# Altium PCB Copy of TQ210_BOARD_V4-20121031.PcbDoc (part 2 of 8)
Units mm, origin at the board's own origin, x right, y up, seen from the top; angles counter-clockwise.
Board outline 191.2 x 131.27 mm, 2 copper layers (TopLayer, BottomLayer); 362 components, 455 nets, 1594 pads, 630 vias.
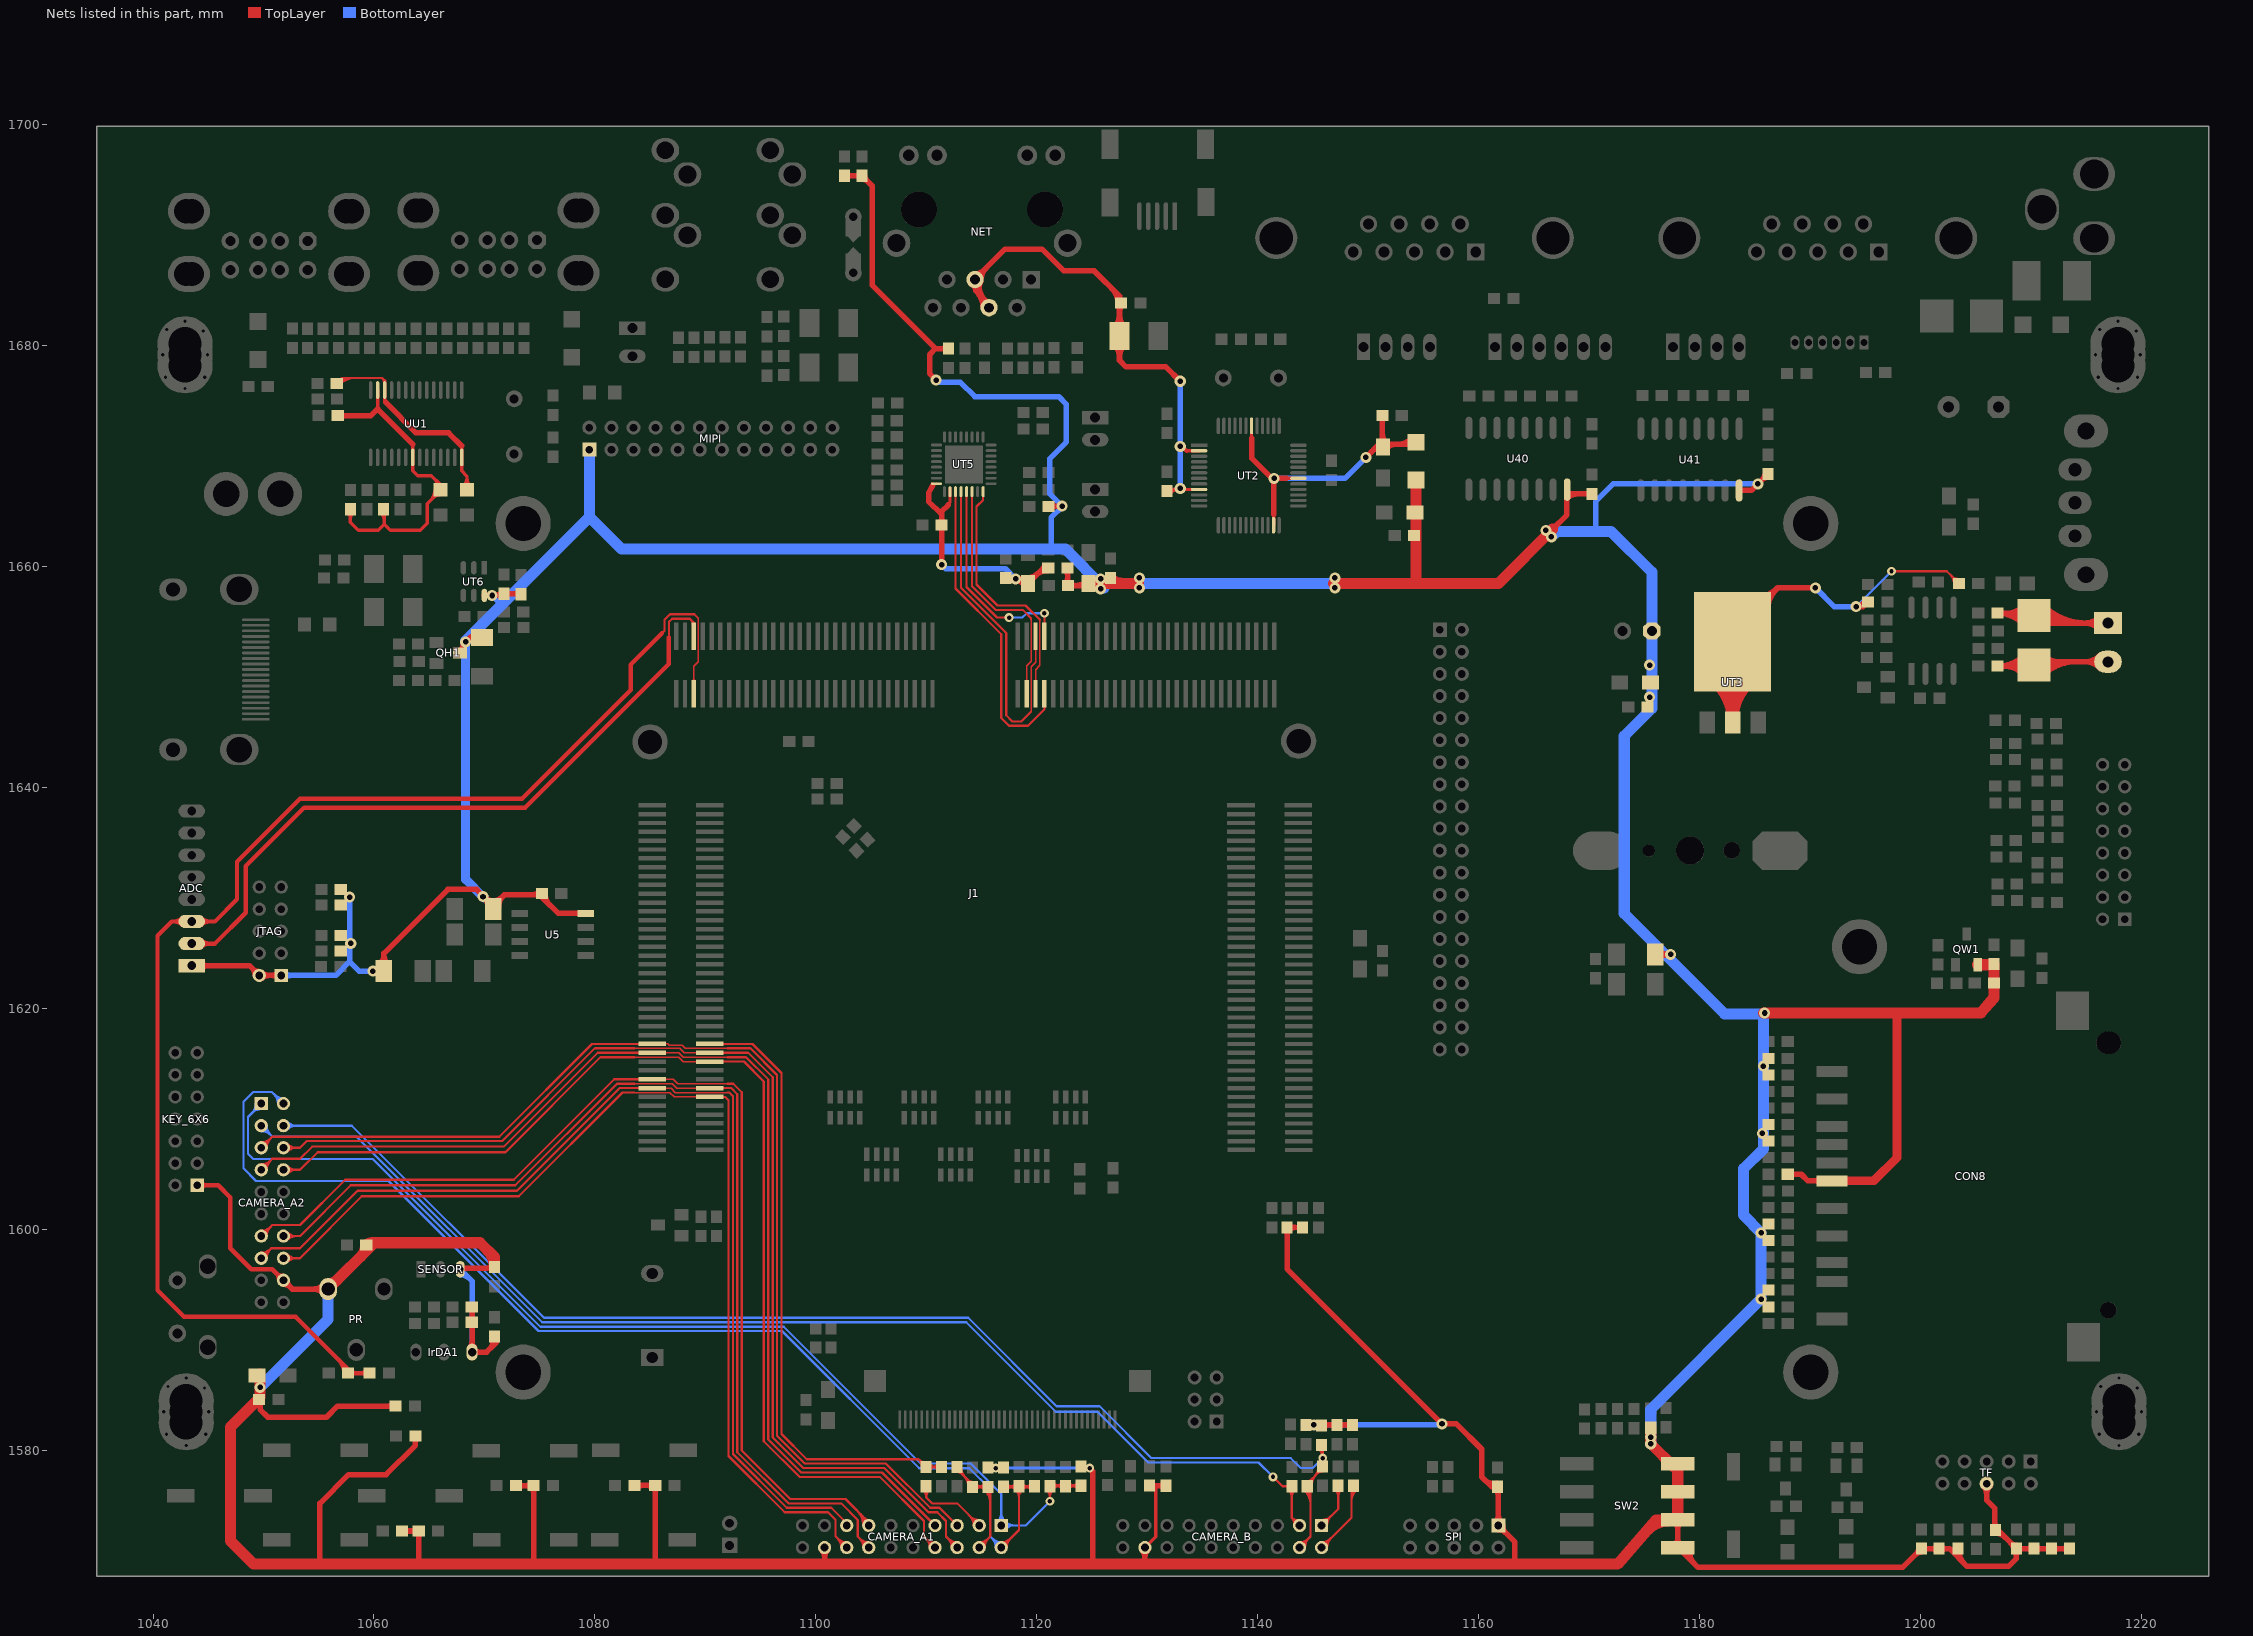
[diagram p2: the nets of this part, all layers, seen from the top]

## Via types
v1: diameter 1, hole 0.5, TopLayer to BottomLayer, 458 vias
v2: diameter 0.8, hole 0.4, TopLayer to BottomLayer, 172 vias

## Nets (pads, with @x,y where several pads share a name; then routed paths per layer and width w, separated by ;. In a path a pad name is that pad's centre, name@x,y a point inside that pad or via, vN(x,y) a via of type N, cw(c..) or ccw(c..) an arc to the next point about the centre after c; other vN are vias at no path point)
1V8_HUB: CU1.1 CU3.2 UU1.12 UU1.28 | length 25.5
  TopLayer w0.2: CU3.2@1056.54,1676.743 cw(c1057.406,1675.877) 1057.406,1677.102 ; CU3.2@1056.631,1676.602 1057.132,1677.102 1060.73,1677.102 1060.965,1676.867 ; CU3.2@1056.681,1676.602 cw(c1057.889,1675.395) 1057.889,1677.102 ; CU3.2@1056.823,1676.46 cw(c1058.372,1674.912) 1058.372,1677.102 ; 1060.726,1677.105 cw(c1060.271,1676.65) UU1.12@1060.915,1676.65 ; 1060.959,1674.943 1060.965,1674.949
  TopLayer w0.3: 1060.965,1674.949 UU1.12@1060.965,1676 1060.965,1676.867 ; 1067.95,1668.688 1068.419,1668.219 CU1.1@1068.419,1666.973 ; UU1.28@1067.95,1669.904 1067.95,1670.949 ; CU1.1@1068.1,1667.291 ccw(c1067.332,1668.059) 1068.419,1668.059 ccw(c1069.505,1668.059) CU1.1@1068.737,1667.291
  TopLayer w0.33: 1067.95,1668.688 UU1.28@1067.95,1669.904
  TopLayer w0.5: 1061.06,1674.917 1063.795,1672.131 1066.767,1672.131 1067.95,1670.949
3V3_HUB: CU2.1 CU5.1 RU18.2 RU19.2 UU1.13 UU1.21 | length 36.1
  TopLayer w0.3: RU18.2@1057.618,1664.911 cw(c1057.02,1664.313) 1057.865,1664.313 cw(c1058.71,1664.313) RU18.2@1058.112,1664.911 ; RU18.2@1057.865,1665.208 1057.865,1664.041 1058.596,1663.31 1060.374,1663.31 1060.933,1663.868 ; 1060.33,1674.289 UU1.13@1060.33,1676 ; RU19.2@1060.618,1664.911 cw(c1059.855,1664.148) 1060.933,1664.148 ; 1060.933,1664.478 cw(c1061.545,1664.478) RU19.2@1061.112,1664.911 ; RU19.2@1060.933,1665.316 1060.933,1663.868 ; 1063.505,1671.114 1063.505,1668.695 1063.95,1668.25 1065.2,1668.25 CU5.1@1065.95,1667.5 ; 1065.111,1665.996 ccw(c1064.13,1666.978) CU5.1@1065.518,1666.978 ; 1065.413,1666.298 cw(c1065.968,1665.743) CU5.1@1065.968,1666.528 ; 1065.421,1668.029 cw(c1064.457,1667.065) CU5.1@1065.818,1666.986 ; CU5.1@1066.056,1666.942 1064.828,1665.714 1064.828,1663.945 1064.193,1663.31 1061.492,1663.31 1060.933,1663.868
  TopLayer w0.5: CU2.1@1056.651,1673.657 1059.698,1673.657 1060.33,1674.289 1063.505,1671.114 ; CU2.1@1056.945,1673.521 cw(c1057.273,1673.194) 1057.273,1673.657 ; CU2.1@1056.945,1673.875 ccw(c1057.471,1674.401) 1057.471,1673.657
3V3_IO: ADC.1 C1.1 C3.1 C5.1 C6.1 C8.1 C9.1 C10.1 C11.1 C12.1 C15.1 C17.1 C111.1 C201.1 C202.1 C403.1 C413.1 C501.1 C517.1 C518.1 CAMERA_A1.18 CAMERA_A2.18 CAMERA_B.18 CM1.1 CM3.1 CMB1.1 CON8.4 D2.1 D3.1 D5.2 D7.2 IrDA1.3 JTAG.1 JTAG.2 KEY_6X6.1 L201.1 L421.1 L501.1 L503.2 L507.2 MIPI.1 PR.3 QH1.C QW1.2 R1.2 R2.2 R3.2 R4.2 R5.2 R6.2 R7.2 R8.2 R33.1 R61.1 R62.1 R63.1 R64.1 R210.1 R211.1 R331.1 RA3.2 RA5.2 RD1.1 RD2.1 RD3.1 RD4.1 RD5.1 RD6.1 RD7.1 RM19.1 RM20.1 RM23.1 RMB19.1 RMB20.1 RMB23.2 RO7.2 RO8.2 RS1.1 RS2.1 RS3.1 RS4.1 RS5.1 RS6.1 RS7.1 RS8.1 RT2.2 RT61.2 RW20.1 RW21.2 SENSOR.3 SPI.1 SW2.5 SW2.6 SW2.7 SW2.8 TF.6 U5.8 U40.16 U41.16 UT3.2 UT3.4 UT6.6 | length 1041.7
  TopLayer w0.2: v2(1197.4,1659.6) 1202.403,1659.6 R331.1@1203.498,1658.505 ; 1202.73,1659.274 cw(c1201.962,1658.505) R331.1@1203.048,1658.505 ; 1202.851,1659.153 ccw(c1203.448,1659.75) R331.1@1203.448,1658.905 ; R331.1@1203.071,1658.932 cw(c1202.645,1658.505) R331.1@1203.248,1658.505
  TopLayer w0.3: KEY_6X6.1@1044.318,1603.682 cw(c1045.086,1602.914) 1045.086,1604 cw(c1045.086,1605.086) KEY_6X6.1@1044.318,1604.318 ; CAMERA_A2.18@1051.35,1595.4 ccw(c1050.264,1595.4) 1051.032,1596.168 ccw(c1051.8,1596.936) CAMERA_A2.18@1051.8,1595.85 ; CAMERA_B.18@1129.8,1571.2 1130.783,1572.183 1130.783,1576.8
  TopLayer w0.4: KEY_6X6.1@1044,1604 1045.9,1604 1047,1602.9 1047,1598.3 1048.9,1596.4 1050.7,1596.4 ; 1050.8,1596.4 CAMERA_A2.18@1051.8,1595.4
  TopLayer w0.5: ADC.1@1043.502,1623.888 1048.728,1623.888 JTAG.2@1049.612,1623.004 ; ADC.1@1044.349,1623.64 cw(c1044.947,1623.043) 1044.947,1623.888 cw(c1044.947,1624.733) ADC.1@1044.349,1624.135 ; JTAG.2@1049.262,1623.004 ccw(c1048.417,1623.004) 1049.015,1623.601 ccw(c1049.612,1624.199) JTAG.2@1049.612,1623.354 ; C5.1@1049.473,1584.423 cw(c1048.926,1583.876) 1049.7,1583.876 ; JTAG.2@1049.612,1623 JTAG.1@1051.7,1623 ; C5.1@1049.7,1584.8 1049.7,1583.7 1050.4,1583 1055.7,1583 1056.711,1584.011 R3.2@1061.992,1584.011 ; JTAG.2@1049.859,1622.756 cw(c1050.448,1622.167) 1050.448,1623 ; JTAG.2@1049.859,1623.251 ccw(c1050.466,1623.857) 1050.466,1623 ; 1050.758,1623 ccw(c1050.758,1623.857) JTAG.1@1051.365,1623.251 ; 1050.776,1623 cw(c1050.776,1622.167) JTAG.1@1051.365,1622.756 ; CAMERA_A2.18@1051.8,1595.05 cw(c1051.8,1594.205) 1052.397,1594.803 cw(c1052.995,1595.4) CAMERA_A2.18@1052.15,1595.4 ; CAMERA_A2.18@1051.8,1595.4 1052.6,1594.6 PR.3@1055.852,1594.6 ; 1055.1,1569.7 1055.1,1575.2 1057.7,1577.8 1061.1,1577.8 1063.75,1580.45 R1.2@1063.75,1581.3 ; PR.3@1055.463,1594.211 ccw(c1054.524,1593.272) 1054.524,1594.6 ccw(c1054.524,1595.928) PR.3@1055.463,1594.989 ; D5.2@1060.546,1624.004 ccw(c1059.693,1624.857) 1060.9,1624.857 ccw(c1062.107,1624.857) D5.2@1061.254,1624.004 ; D5.2@1060.9,1623.4 1060.9,1625 1066.7,1630.8 1069.3,1630.8 1070.8,1629.3 1071.8,1630.3 1075,1630.3 1076.688,1628.612 U5.8@1079.194,1628.612 ; 1061.27,1584.011 cw(c1061.27,1583.37) R3.2@1061.723,1583.823 ; 1061.323,1584.011 ccw(c1061.323,1584.577) R3.2@1061.723,1584.177 ; R2.2@1062.55,1572.7 R4.2@1064.05,1572.7 1064.05,1569.7 ; R2.2@1062.777,1572.523 cw(c1063.204,1572.096) 1063.204,1572.7 cw(c1063.204,1573.304) R2.2@1062.777,1572.877 ; R1.2@1063.573,1581.123 cw(c1063.146,1580.696) 1063.75,1580.696 cw(c1064.354,1580.696) R1.2@1063.927,1581.123 ; R4.2@1063.823,1572.523 ccw(c1063.396,1572.096) 1063.396,1572.7 ccw(c1063.396,1573.304) R4.2@1063.823,1572.877 ; R4.2@1063.873,1572.523 cw(c1063.446,1572.096) 1064.05,1572.096 cw(c1064.654,1572.096) R4.2@1064.227,1572.523 ; QH1.C@1067.782,1652.401 ccw(c1067.376,1653) v1@1068.1,1653 ; SENSOR.3@1067.808,1596.4 1067.908,1596.5 1070.145,1596.5 ; SENSOR.3@1067.914,1596.294 cw(c1068.412,1595.796) 1068.412,1596.5 ; QH1.C@1068.1,1652.1 v1@1068.1,1653 ; v1@1068.275,1653.175 cw(c1068.775,1652.675) D2.1@1069.229,1653.217 ; v1@1068.334,1653.234 cw(c1069.283,1652.284) 1069.55,1653.6 ccw(c1069.127,1653.095) 1068.661,1653.561 ; IrDA1.3@1068.698,1589.336 ccw(c1068.257,1589.777) 1068.88,1589.777 ccw(c1069.503,1589.777) IrDA1.3@1069.062,1589.336 ; RA3.2@1068.723,1591.423 cw(c1068.345,1591.045) 1068.88,1591.045 ; RA3.2@1068.723,1591.777 ccw(c1068.345,1592.155) 1068.88,1592.155 ; RA5.2@1068.723,1592.823 cw(c1068.345,1592.445) 1068.88,1592.445 ; RA5.2@1068.85,1593 1068.88,1592.97 IrDA1.3@1068.88,1588.9 ; 1068.88,1590.948 cw(c1069.552,1590.948) RA3.2@1069.077,1591.423 ; 1068.88,1592.252 ccw(c1069.552,1592.252) RA3.2@1069.077,1591.777 ; 1068.88,1592.348 cw(c1069.552,1592.348) RA5.2@1069.077,1592.823 ; IrDA1.3@1069,1588.9 1070.2,1588.9 1070.9,1589.6 CM1.1@1070.9,1590.3 ; IrDA1.3@1069.062,1588.718 cw(c1069.503,1588.277) 1069.503,1588.9 cw(c1069.503,1589.523) IrDA1.3@1069.062,1589.082 ; D2.1@1069.113,1653.357 ccw(c1068.7,1653.128) 1068.7,1653.6 ; D2.1@1069.113,1653.843 cw(c1068.7,1654.072) 1068.7,1653.6 ; D2.1@1069.8,1653.6 1068.7,1653.6 ; v1@1069.911,1630.189 cw(c1068.972,1629.25) D7.2@1070.3,1629.25 ; UT6.6@1069.995,1657.412 RT61.2@1071.588,1657.412 ; v1@1070.032,1630.068 ccw(c1070.8,1630.836) 1070.8,1629.75 ccw(c1070.8,1630.836) 1071.568,1630.068 ; 1070.525,1589.225 ccw(c1069.963,1589.787) CM1.1@1070.676,1590.139 ; C501.1@1070.6,1596.4 C501.1@1070.7,1596.3 ; CM1.1@1070.723,1590.073 cw(c1070.296,1589.646) 1070.9,1589.646 cw(c1071.504,1589.646) CM1.1@1071.077,1590.073 ; v1@1070.948,1657.412 ccw(c1070.948,1658.35) RT61.2@1071.612,1657.687 ; 1071.018,1589.718 ccw(c1070.623,1590.113) CM1.1@1071.124,1590.361 ; D7.2@1071.3,1629.25 cw(c1072.628,1629.25) 1071.689,1630.189 ; RT61.2@1071.789,1657.56 CM3.1@1073.253,1657.56 ; RT61.2@1071.965,1657.383 cw(c1072.392,1656.956) 1072.392,1657.56 cw(c1072.392,1658.164) RT61.2@1071.965,1657.737 ; 1072.697,1657.56 ccw(c1072.697,1658.166) CM3.1@1073.125,1657.737 ; 1072.7,1657.56 cw(c1072.7,1656.959) CM3.1@1073.125,1657.384 ; R5.2@1072.85,1576.8 R6.2@1074.45,1576.8 1074.45,1569.7 ; R5.2@1073.077,1576.623 cw(c1073.504,1576.196) 1073.504,1576.8 cw(c1073.504,1577.404) R5.2@1073.077,1576.977 ; R6.2@1074.223,1576.623 ccw(c1073.796,1576.196) 1073.796,1576.8 ccw(c1073.796,1577.404) R6.2@1074.223,1576.977 ; R6.2@1074.273,1576.623 cw(c1073.846,1576.196) 1074.45,1576.196 cw(c1075.054,1576.196) R6.2@1074.627,1576.623 ; 1074.305,1630.3 ccw(c1074.305,1631.245) C9.1@1074.973,1630.577 ; C9.1@1075.5,1630.4 ccw(c1076.949,1630.4) 1075.924,1629.376 ; R7.2@1083.574,1576.824 R8.2@1085.474,1576.824 1085.474,1569.7 ; R7.2@1083.801,1576.647 cw(c1084.228,1576.22) 1084.228,1576.824 cw(c1084.228,1577.428) R7.2@1083.801,1577.001 ; R8.2@1085.247,1576.647 ccw(c1084.82,1576.22) 1084.82,1576.824 ccw(c1084.82,1577.428) R8.2@1085.247,1577.001 ; R8.2@1085.297,1576.647 cw(c1084.87,1576.22) 1085.474,1576.22 cw(c1086.078,1576.22) R8.2@1085.651,1576.647 ; CAMERA_A1.18@1100.553,1570.953 cw(c1099.955,1570.355) 1100.8,1570.355 cw(c1101.645,1570.355) CAMERA_A1.18@1101.047,1570.953 ; 1100.8,1569.9 CAMERA_A1.18@1100.8,1571.2 ; R210.1@1102.6,1695.4 R211.1@1103.9,1695.4 ; R210.1@1102.777,1695.223 cw(c1103.204,1694.796) 1103.204,1695.4 cw(c1103.204,1696.004) R210.1@1102.777,1695.577 ; R211.1@1104.023,1695.223 ccw(c1103.596,1694.796) 1103.596,1695.4 ccw(c1103.596,1696.004) R211.1@1104.023,1695.577 ; R211.1@1104.2,1695.1 cw(c1104.2,1694.376) 1104.712,1694.888 ; R211.1@1104.2,1695.4 1105.1,1694.5 1105.1,1685.5 1110.85,1679.75 ; R211.1@1104.45,1695.35 ccw(c1104.933,1695.35) R211.1@1104.591,1695.009 ; v1(1110.9,1676.9) 1110.3,1677.5 1110.3,1679.2 1110.85,1679.75 ; L503.2@1111.823,1679.573 ccw(c1111.396,1679.146) 1111.396,1679.75 ccw(c1111.396,1680.354) L503.2@1111.823,1679.927 ; L503.2@1112,1679.75 1110.85,1679.75 ; L507.2@1121.078,1665.476 v1@1122.324,1665.476 ; L507.2@1121.305,1665.299 cw(c1121.731,1664.872) 1121.731,1665.476 cw(c1121.731,1666.08) L507.2@1121.305,1665.653 ; RT2.2@1122.623,1658.477 ccw(c1122.196,1658.904) 1122.8,1658.904 ccw(c1123.404,1658.904) RT2.2@1122.977,1658.477 ; L501.1@1122.623,1659.723 cw(c1122.196,1659.296) 1122.8,1659.296 cw(c1123.404,1659.296) L501.1@1122.977,1659.723 ; RT2.2@1122.8,1658.35 L501.1@1122.8,1659.9 ; RT2.2@1122.85,1658.3 C517.1@1124.7,1658.3 ; RT2.2@1123.077,1658.123 cw(c1123.504,1657.696) 1123.504,1658.3 cw(c1123.504,1658.904) RT2.2@1123.077,1658.477 ; 1123.594,1658.3 ccw(c1123.594,1659.479) C517.1@1124.428,1658.645 ; 1123.947,1658.3 cw(c1123.947,1657.62) C517.1@1124.428,1658.101 ; RM20.1@1124,1578.4 v2(1124.8,1578.4) 1125.1,1578.1 1125.1,1569.7 ; CAMERA_B.18@1129.553,1570.953 cw(c1128.955,1570.355) 1129.8,1570.355 cw(c1130.645,1570.355) CAMERA_B.18@1130.047,1570.953 ; 1129.7,1569.9 1129.8,1570 CAMERA_B.18@1129.8,1571.2 ; C11.1@1130.22,1576.8 R33.1@1131.7,1576.8 ; R33.1@1131.523,1576.623 ccw(c1131.096,1576.196) 1131.096,1576.8 ccw(c1131.096,1577.404) R33.1@1131.523,1576.977 ; RO8.2@1142.501,1599.945 cw(c1142.075,1599.518) 1142.678,1599.518 cw(c1143.282,1599.518) RO8.2@1142.855,1599.945 ; RO8.2@1142.678,1600.172 1142.678,1596.422 v1(1156.7,1582.4) ; RO8.2@1142.7,1600.2 RO7.2@1143.778,1600.172 ; RO8.2@1142.85,1599.991 cw(c1143.333,1599.482) 1143.351,1600.183 ; RO8.2@1142.86,1600.344 ccw(c1143.226,1600.693) 1143.213,1600.187 ; C8.1@1144.395,1582.311 1145.795,1582.311 1145.805,1582.3 RMB19.1@1148.8,1582.3 ; C8.1@1144.571,1582.134 cw(c1144.998,1581.707) 1144.998,1582.311 cw(c1144.998,1582.914) C8.1@1144.571,1582.487 ; v1@1145.171,1582.311 cw(c1145.171,1581.671) RMB23.2@1145.623,1582.123 ; v1@1145.222,1582.311 ccw(c1145.222,1582.878) RMB23.2@1145.623,1582.477 ; RMB23.2@1145.977,1582.123 cw(c1146.404,1581.696) 1146.404,1582.3 cw(c1146.404,1582.904) RMB23.2@1145.977,1582.477 ; RMB20.1@1147.023,1582.123 ccw(c1146.596,1581.696) 1146.596,1582.3 ccw(c1146.596,1582.904) RMB20.1@1147.023,1582.477 ; RMB20.1@1147.377,1582.123 cw(c1147.804,1581.696) 1147.804,1582.3 cw(c1147.804,1582.904) RMB20.1@1147.377,1582.477 ; RMB19.1@1148.423,1582.123 ccw(c1147.996,1581.696) 1147.996,1582.3 ccw(c1147.996,1582.904) RMB19.1@1148.423,1582.477 ; L201.1@1153.992,1667.486 cw(c1153.118,1666.612) 1154.354,1666.612 cw(c1155.59,1666.612) L201.1@1154.716,1667.486 ; C202.1@1154.039,1662.647 cw(c1153.277,1661.885) 1154.354,1661.885 ; C202.1@1154.039,1663 ccw(c1153.277,1663.762) 1154.354,1663.762 ; C201.1@1154.12,1664.651 cw(c1153.556,1664.087) 1154.354,1664.087 ; C201.1@1154.12,1665.196 ccw(c1153.556,1665.76) 1154.354,1665.76 ; 1154.354,1658.546 1154.4,1658.5 ; 1154.354,1663.901 cw(c1155.415,1663.901) C201.1@1154.665,1664.651 ; 1154.354,1665.946 ccw(c1155.415,1665.946) C201.1@1154.665,1665.196 ; v1@1156.7,1582.3 v1(1156.7,1582.4) ; 1160.585,1577.315 ccw(c1161.403,1578.132) C12.1@1161.655,1577.004 ; C12.1@1161.515,1576.554 ccw(c1161.19,1576.294) 1161.19,1576.71 ; C12.1@1161.515,1576.866 cw(c1161.19,1577.126) 1161.19,1576.71 ; SPI.1@1161.527,1573.471 ccw(c1160.844,1574.151) 1161.807,1574.154 ; C12.1@1161.534,1576.483 cw(c1160.891,1575.836) 1161.803,1575.839 ; C12.1@1161.71,1576.71 1161.19,1576.71 ; SPI.1@1161.8,1572.815 cw(c1161.8,1571.886) 1162.457,1572.543 cw(c1163.114,1573.2) SPI.1@1162.185,1573.2 ; C12.1@1161.8,1576.8 1161.81,1573.19 1163.3,1571.7 1163.3,1569.8 ; 1161.807,1574.105 ccw(c1162.703,1574.108) SPI.1@1162.071,1573.473 ; 1166.7,1663.4 1168,1664.7 U40.16@1168,1666.9 ; U40.16@1168.067,1666.239 cw(c1168.938,1665.369) 1168.938,1666.6 ; U40.16@1168.1,1666.6 C403.1@1170.3,1666.6 ; C403.1@1170.123,1666.423 ccw(c1169.696,1665.996) 1169.696,1666.6 ccw(c1169.696,1667.204) C403.1@1170.123,1666.777 ; D3.1@1176,1624.9 v1(1177.4,1624.9) ; D3.1@1176.354,1624.546 cw(c1177.207,1623.693) 1177.207,1624.9 cw(c1177.207,1626.107) D3.1@1176.354,1625.254 ; SW2.8@1177.722,1578.478 1178.044,1578.156 ; SW2.5@1177.797,1571.427 ccw(c1177.199,1572.025) 1178.044,1572.025 ccw(c1178.889,1572.025) SW2.5@1178.291,1571.427 ; SW2.6@1177.797,1573.473 cw(c1177.199,1572.875) 1178.044,1572.875 cw(c1178.889,1572.875) SW2.6@1178.291,1573.473 ; SW2.5@1177.9,1571.662 ccw(c1178.163,1571.541) SW2.5@1177.958,1571.336 ; SW2.5@1178.044,1571.18 SW2.6@1178.044,1573.7 ; SW2.5@1178.044,1571.25 1179.894,1569.4 1198.4,1569.4 RD1.1@1200.1,1571.1 1202.65,1571.1 1204.25,1569.5 1208,1569.5 1208.7,1570.2 RD4.1@1208.7,1571.1 ; SW2.5@1178.354,1571.452 ccw(c1178.856,1571.22) SW2.5@1178.465,1570.829 ; SW2.5@1178.808,1571.243 ccw(c1179.55,1570.9) 1178.972,1570.322 ; SW2.5@1179.262,1571.033 ccw(c1180.244,1570.58) 1179.479,1569.815 ; U41.16@1183.6,1666.912 1184.712,1666.912 C413.1@1186.2,1668.4 ; UT3.4@1183.654,1656.353 ccw(c1184.314,1658.527) UT3.4@1185.92,1656.92 ; UT3.4@1183.799,1656.831 ccw(c1184.589,1659.432) 1186.51,1657.51 ; UT3.4@1183.944,1657.31 ccw(c1184.863,1660.336) 1187.1,1658.1 ccw(c1189.54,1655.66) UT3.4@1186.172,1654.908 ; UT3.4@1185.684,1654.799 cw(c1188.488,1655.425) UT3.4@1186.456,1657.456 ; 1185.688,1667.888 cw(c1186.2,1667.376) C413.1@1186.2,1668.1 ; C413.1@1185.809,1668.009 ccw(c1185.467,1668.35) C413.1@1185.95,1668.35 ; UT3.4@1186,1657 1187.1,1658.1 v1(1190.5,1658.1) ; C3.1@1188,1605 1189.229,1605 1189.824,1604.405 CON8.4@1191.995,1604.405 ; C3.1@1188.227,1604.823 cw(c1188.654,1604.396) 1188.654,1605 cw(c1188.654,1605.604) C3.1@1188.227,1605.177 ; CON8.4@1190.918,1604.228 ccw(c1190.491,1603.801) 1190.491,1604.405 ccw(c1190.491,1605.009) CON8.4@1190.918,1604.582 ; L421.1@1195.005,1656.906 cw(c1194.2,1657.293) v1(1194.2,1656.4) 1194.8,1656.4 L421.1@1195.2,1656.8 ; 1199.588,1570.588 cw(c1200.1,1570.076) RD1.1@1200.1,1570.8 ; RD1.1@1199.709,1570.709 ccw(c1199.367,1571.05) RD1.1@1199.85,1571.05 ; RD1.1@1200.277,1570.923 cw(c1200.704,1570.496) 1200.704,1571.1 cw(c1200.704,1571.704) RD1.1@1200.277,1571.277 ; RD2.1@1201.523,1570.923 ccw(c1201.096,1570.496) 1201.096,1571.1 ccw(c1201.096,1571.704) RD2.1@1201.523,1571.277 ; RD2.1@1201.877,1570.923 cw(c1202.304,1570.496) 1202.304,1571.1 cw(c1202.304,1571.704) RD2.1@1201.877,1571.277 ; RD3.1@1203.163,1571.13 ccw(c1203.818,1570.909) 1203.33,1570.42 ; RD3.1@1203.637,1570.97 ccw(c1204.672,1570.622) 1203.9,1569.85 ; TF.6@1205.739,1576.717 cw(c1205.082,1576.059) 1206.011,1576.059 cw(c1206.94,1576.059) TF.6@1206.283,1576.717 ; TF.6@1206.011,1576.989 1206.011,1575.489 1206.75,1574.75 1206.75,1573 1206.8,1573 RD4.1@1208.7,1571.1 ; 1206.072,1623.97 ccw(c1206.072,1624.602) RW21.2@1206.518,1624.155 ; 1206.111,1623.97 cw(c1206.111,1623.395) 1206.518,1623.802 cw(c1206.131,1623.415) 1206.679,1623.415 ; RW20.1@1206.502,1622.482 ccw(c1206.075,1622.909) 1206.679,1622.909 ccw(c1207.282,1622.909) RW20.1@1206.855,1622.482 ; RW21.2@1206.637,1623.97 RW21.2@1206.679,1623.929 ; 1206.679,1623.335 cw(c1207.338,1623.335) RW21.2@1206.872,1623.802 ; RW21.2@1206.679,1624.012 RW21.2@1206.695,1624.029 ; 1206.75,1573.574 ccw(c1207.524,1573.574) C6.1@1206.977,1573.027 ; C6.1@1206.8,1572.5 cw(c1206.8,1571.293) 1207.654,1572.146 ; 1208.188,1571.612 ccw(c1208.7,1572.124) RD4.1@1208.7,1571.4 ; RD4.1@1208.309,1571.491 cw(c1207.967,1571.15) RD4.1@1208.45,1571.15 ; RD4.1@1208.523,1570.873 cw(c1208.096,1570.446) 1208.7,1570.446 cw(c1209.304,1570.446) RD4.1@1208.877,1570.873 ; RD4.1@1208.877,1570.923 cw(c1209.304,1570.496) 1209.304,1571.1 cw(c1209.304,1571.704) RD4.1@1208.877,1571.277 ; RD5.1@1210.123,1570.923 ccw(c1209.696,1570.496) 1209.696,1571.1 ccw(c1209.696,1571.704) RD5.1@1210.123,1571.277 ; RD5.1@1210.477,1570.923 cw(c1210.904,1570.496) 1210.904,1571.1 cw(c1210.904,1571.704) RD5.1@1210.477,1571.277 ; RD6.1@1211.723,1570.923 ccw(c1211.296,1570.496) 1211.296,1571.1 ccw(c1211.296,1571.704) RD6.1@1211.723,1571.277 ; RD6.1@1212.077,1570.923 cw(c1212.504,1570.496) 1212.504,1571.1 cw(c1212.504,1571.704) RD6.1@1212.077,1571.277 ; RD7.1@1213.323,1570.923 ccw(c1212.896,1570.496) 1212.896,1571.1 ccw(c1212.896,1571.704) RD7.1@1213.323,1571.277 ; RD7.1@1213.5,1571.1 RD4.1@1208.7,1571.1 ; v1@1068.1,1653 1068.7,1653.6 ; 1070.145,1596.5 ccw(c1070.145,1597.31) 1070.718,1596.737 cw(c1070.145,1597.31) 1070.145,1596.5 ; v1(1156.7,1582.4) 1158,1582.4 1160.3,1580.1 1160.3,1577.6 1161.19,1576.71
  TopLayer w0.8: CON8.4@1191.9,1604.405 1195.805,1604.405 1197.9,1606.5 1197.9,1619.6
  TopLayer w1: 1047,1571.8 1049.1,1569.7 1172.6,1569.7 1176.1,1573.7 SW2.6@1178,1573.7 ; 1047,1571.9 1047,1582.1 1049.7,1584.8 C15.1@1049.7,1586.9 ; C15.1@1049.443,1586.69 cw(c1048.823,1586.07) v1@1049.7,1586.07 ; PR.3@1055.852,1594.6 1060.052,1598.8 ; PR.3@1055.852,1595.1 ccw(c1055.852,1596.307) 1056.706,1595.454 ; 1058.824,1597.572 ccw(c1057.797,1598.6) CMB1.1@1059.25,1598.6 ; 1070.297,1598.103 cw(c1068.855,1596.661) C501.1@1070.895,1596.661 ; C501.1@1070.895,1596.611 1070.895,1597.505 1069.6,1598.8 1060.052,1598.8 ; C517.1@1124.7,1658.5 v1@1129.2,1658.5 ; v1@1125.614,1658.5 ccw(c1125.614,1660.036) 1126.7,1658.95 ccw(c1127.786,1660.036) 1127.786,1658.5 ; v1@1146.9,1658.5 1161.8,1658.5 1166.7,1663.4 ; 1154.354,1658.546 L201.1@1154.354,1667.848 ; 1175.176,1572.643 cw(c1177.342,1570.748) SW2.6@1177.151,1573.62 ; 1175.519,1573.036 cw(c1176.856,1571.866) SW2.6@1177.129,1573.621 ; C1.1@1175.6,1582.05 v1(1175.6,1580.6) SW2.8@1177.722,1578.478 ; 1176.792,1579.408 cw(c1176.185,1578.8) SW2.8@1177.044,1578.8 ; SW2.6@1178.044,1573.72 1178.044,1578.156 ; UT3.4@1181.116,1649.865 cw(c1177.916,1645.9) UT3.2@1183.011,1645.9 cw(c1188.145,1645.9) UT3.4@1184.898,1649.876 ; UT3.4@1181.744,1650.644 cw(c1179.605,1647.992) 1183.011,1647.992 ; UT3.4@1183,1649.8 1183.011,1649.789 UT3.2@1183.011,1645.9 ; 1183.011,1648.008 cw(c1186.424,1648.008) UT3.4@1184.265,1650.651 ; v1@1185.8,1619.6 1205.5,1619.6 1206.679,1620.979 RW20.1@1206.679,1622.305 RW21.2@1206.679,1624.012 ; QW1.2@1205.206,1623.97 RW21.2@1206.637,1623.97 ; CMB1.1@1059.35,1598.6 cw(c1059.833,1598.117) 1059.833,1598.8 ccw(c1059.833,1598.117) CMB1.1@1059.35,1598.6 ; CMB1.1@1059.35,1598.6 ccw(c1059.521,1599.331) 1060.052,1598.8
  BottomLayer w0.2: v1(1194.2,1656.4) v2(1197.4,1659.6) v2@1197.6,1659.6
  BottomLayer w0.3: v2(1116.3,1578.4) v2(1124.8,1578.4)
  BottomLayer w0.5: JTAG.1@1051.612,1623.004 1056.544,1623.004 1057.8,1624.259 ; JTAG.1@1051.86,1622.756 cw(c1052.457,1622.159) 1052.457,1623.004 cw(c1052.457,1623.849) JTAG.1@1051.86,1623.251 ; v1(1057.8,1630.1) 1057.8,1624.259 ; v1(1059.9,1623.4) 1058.659,1623.4 1057.8,1624.259 ; SENSOR.3@1067.808,1595.9 cw(c1067.808,1594.693) 1068.662,1595.546 ; SENSOR.3@1067.808,1596.4 1068.88,1595.328 IrDA1.3@1068.88,1588.9 ; IrDA1.3@1068.698,1589.336 ccw(c1068.257,1589.777) 1068.88,1589.777 ccw(c1069.503,1589.777) IrDA1.3@1069.062,1589.336 ; v1(1070.7,1657.4) 1071.55,1656.55 ; v1@1111.2,1676.7 1113.1,1676.7 1114.4,1675.4 1122,1675.4 1122.7,1674.7 1122.7,1671.3 1121.2,1669.8 1121.2,1666.6 v1(1122.3,1665.5) ; 1121.3,1661.6 1121.3,1664.452 v1@1122.324,1665.476 ; v1(1145.1,1582.311) v1@1156.689,1582.311 ; v1@1166.4,1663.2 v1@1166.5,1663.2 ; 1170.6,1663.3 1170.6,1665.9 1172.2,1667.5 v1(1185.3,1667.5) ; v1(1190.5,1658.1) 1192.2,1656.4 v1(1194.2,1656.4)
  BottomLayer w0.8: v1(1068.3,1653.2) 1068.3,1631.7 v1@1070,1630
  BottomLayer w1: v1(1049.7,1585.7) 1055.852,1591.852 PR.3@1055.852,1594.6 ; v1@1068.3,1653.3 1079.5,1664.5 ; MIPI.1@1079.5,1670.6 1079.5,1664.5 ; v1@1126.1,1658.1 1122.6,1661.6 1082.4,1661.6 1079.5,1664.5 ; v1@1129.3,1658.5 1147.3,1658.5 ; v1@1166.5,1663.2 1172,1663.2 1175.694,1659.506 1175.694,1647.194 1173.2,1644.7 1173.2,1628.6 1182.3,1619.5 1185.8,1619.5 1185.8,1607.3 1184,1605.5 1184,1601.3 v1(1185.6,1599.7) v1@1185.6,1593.8 ; v1@1166.54,1663.34 1166.59,1663.29 1166.68,1663.2 v1@1166.89,1662.99 ; v1(1175.6,1580.6) 1175.6,1583.7 v1(1185.6,1593.7)
  other v1: 1175.6,1581.2 1185.7,1608.7 1185.8,1614.8 1185.9,1619.6 1057.9,1625.9 1069.871,1630.129 1175.5,1648.2 1175.5,1651.1 1125.8,1658 1129.3,1658.1 1147,1658.1 1125.8,1658.9 1129.3,1659 1147,1659 1166.6,1662.7 1166.1,1663.3
33V_AC97: C519.1 C520.1 C521.1 L501.2 UT5.8 UT5.10 | length 29.8
  TopLayer w0.2: 1110.598,1667.394 UT5.8@1110.928,1667.524
  TopLayer w0.3: 1112,1665.6 1112.153,1665.853 UT5.10@1112.153,1666.799 ; UT5.10@1112.148,1667.115 1112.149,1666.799 1112.153,1666.053
  TopLayer w0.5: 1110.598,1667.394 1110.228,1666.717 1110.228,1665.872 1111.4,1664.8 ; C520.1@1111.223,1663.623 cw(c1110.796,1663.196) 1111.4,1663.196 cw(c1112.004,1663.196) C520.1@1111.577,1663.623 ; C520.1@1111.223,1663.977 ccw(c1110.796,1664.404) 1111.4,1664.404 ccw(c1112.004,1664.404) C520.1@1111.577,1663.977 ; v1(1111.4,1660.2) 1111.4,1665 1112,1665.6 ; C521.1@1117.1,1658.9 1119.6,1658.9 1120.6,1659.9 L501.2@1121.05,1659.9 ; C521.1@1117.377,1659.127 ccw(c1117.924,1659.674) v1@1117.924,1658.9 ; C521.1@1117.611,1658.9 cw(c1117.611,1657.038) C519.1@1118.928,1658.355 ; C519.1@1119.2,1659.012 ccw(c1119.2,1660.248) 1120.074,1659.374 ; C519.1@1119.585,1658.627 cw(c1120.208,1658.627) C519.1@1119.767,1659.067 ; 1119.89,1659.19 cw(c1121,1658.081) L501.2@1121,1659.65
  BottomLayer w0.5: v1(1111.4,1660.2) 1111.78,1659.82 1117.18,1659.82 v1(1118.1,1658.9)
A1: 485.1 D421.2 R429.1 | length 30.9
  TopLayer w0.5: R429.1@1207.227,1655.623 cw(c1207.654,1655.196) 1207.654,1655.8 cw(c1207.654,1656.404) R429.1@1207.227,1655.977 ; 1207.765,1655.8 ccw(c1207.765,1658.135) D421.2@1209.416,1656.484 ; 1208.138,1655.8 cw(c1208.138,1653.615) D421.2@1209.748,1655.093 ; D421.2@1209.379,1654.755 ccw(c1207,1652.57) R429.1@1207,1655.8 1210.1,1655.8 1211,1654.9 485.1@1217,1654.9 ; D421.2@1210.477,1655.777 ccw(c1212.593,1657.893) 1212.593,1654.9 ; D421.2@1210.83,1656.13 ccw(c1213.801,1659.101) 1213.801,1654.9 ; D421.2@1211.184,1654.716 cw(c1211.628,1654.272) D421.2@1211.628,1654.9 ; D421.2@1211.184,1656.484 ccw(c1215.008,1660.308) 1215.008,1654.9 ; 485.1@1216.22,1654.37 ccw(c1214.939,1653.089) 1214.939,1654.9 ccw(c1214.939,1656.711) 485.1@1216.22,1655.43
AC97_BITCLK: J1.145 UT5.12 | length 31.8
  TopLayer w0.135: 1119.497,1646.903 1119.497,1650.942 1119.896,1651.34 J1.145@1119.896,1653.706
  TopLayer w0.2: UT5.12@1113.153,1666.799 1113.153,1658.097 1117.25,1654 1117.25,1646.55 1117.8,1646 1118.6,1646 1119.5,1646.9
AC97_RESETN: J1.148 UT5.11 | length 28.8
  TopLayer w0.2: UT5.11@1112.653,1666.799 1112.653,1658.032 1116.8,1653.884 1116.8,1646.3 1117.5,1645.6 1119.213,1645.6 1120.706,1647.093 J1.148@1120.706,1648.495 ; J1.148@1120.625,1647.385 cw(c1120.429,1647.189) 1120.706,1647.189 ; 1120.706,1647.239 cw(c1120.912,1647.239) J1.148@1120.766,1647.385
AC97_SDI: J1.146 UT5.16 | length 22.6
  TopLayer w0.135: J1.146@1119.896,1648.506 1119.896,1650.678 1120.295,1651.078 1120.295,1655.2
  TopLayer w0.2: UT5.16@1115.153,1666.799 1115.153,1666.053 1114.553,1665.453 1114.553,1658.394 1116.447,1656.5 1118.995,1656.5 1120.295,1655.2
AC97_SDO: J1.144 UT5.14 | length 22.2
  TopLayer w0.135: J1.144@1119.096,1648.506 1119.096,1651.042 1119.497,1651.444 1119.497,1655.335
  TopLayer w0.2: UT5.14@1114.153,1666.799 1114.153,1658.229 1116.281,1656.1 1118.732,1656.1 1119.497,1655.335 ; 1119.497,1655.256 1119.497,1655.303
AC97_SYNC: J1.147 UT5.13 | length 19.4
  TopLayer w0.2: UT5.13@1113.653,1666.799 1113.653,1658.163 1116.416,1655.4 v2(1117.5,1655.4) ; v2(1120.7,1655.8) J1.147@1120.706,1653.695
  BottomLayer w0.2: v2(1117.5,1655.4) 1118.7,1655.4 1119.1,1655.8 v2(1120.7,1655.8) v2@1120.5,1655.6
ADCIN0: ADC.2 J1.85 | length 65.8
  TopLayer w0.2: 1086.7,1653.6 1086.7,1655 1087,1655.3 1088.6,1655.3 1088.975,1654.925 J1.85@1088.975,1653.687 ; 1088.661,1655.239 cw(c1088.168,1654.747) J1.85@1088.865,1654.747
  TopLayer w0.4: ADC.2@1043.502,1625.888 1045.6,1625.888 1048.4,1628.688 1048.4,1632.9 1053.7,1638.2 1073.7,1638.2 1086.7,1651.2 1086.7,1653.6 ; ADC.2@1044.385,1625.605 cw(c1045.067,1624.922) 1045.067,1625.888 cw(c1045.067,1626.853) ADC.2@1044.385,1626.171
ADCIN1: ADC.3 CT6.2 J1.86 RA1.1 | length 134.2
  TopLayer w0.135: J1.86@1088.871,1649.641 ccw(c1088.645,1649.867) 1088.965,1649.867 ccw(c1089.284,1649.867) J1.86@1089.058,1649.641 ; J1.86@1088.965,1648.497 1088.965,1651.013 1089.366,1651.414 1089.366,1655.329 1088.995,1655.7
  TopLayer w0.2: 1086.078,1653.978 1086.3,1654.2 1086.3,1655.2 1086.8,1655.7 1088.995,1655.7
  TopLayer w0.4: ADC.3@1042.619,1627.605 ccw(c1041.936,1626.922) 1041.936,1627.888 ccw(c1041.936,1628.853) ADC.3@1042.619,1628.171 ; ADC.3@1044.385,1627.605 cw(c1045.067,1626.922) 1045.067,1627.888 cw(c1045.067,1628.853) ADC.3@1044.385,1628.171 ; 1056.805,1588.195 cw(c1055.61,1587) CT6.2@1057.3,1587 ; 1057.488,1587.512 cw(c1056.976,1587) CT6.2@1057.7,1587 ; CT6.2@1057.912,1586.788 cw(c1058.424,1586.276) 1058.424,1587 cw(c1058.424,1587.724) CT6.2@1057.912,1587.212 ; RA1.1@1059.338,1586.788 ccw(c1058.826,1586.276) 1058.826,1587 ccw(c1058.826,1587.724) RA1.1@1059.338,1587.212 ; RA1.1@1059.6,1587 1058,1587 1052.9,1592.1 1042.8,1592.1 1040.4,1594.5 1040.4,1626.6 1041.688,1627.888 1045.6,1627.888 1047.6,1629.888 1047.6,1633.3 1053.3,1639 1073.4,1639 1083.244,1648.844 1083.244,1651.144 1086.078,1653.978
AVDD25V: C210.1 C211.2 C212.2 NET.4 NET.5 UT2.2 UT2.9 | length 63.1
  TopLayer w0.2: C211.2@1131.9,1667.1 C211.2@1131.996,1667.004
  TopLayer w0.3: C211.2@1131.996,1667.004 UT2.9@1134.703,1667.004 ; C211.2@1132.047,1666.653 cw(c1132.897,1665.803) v1@1132.897,1667.004 ; C211.2@1132.047,1667.147 ccw(c1132.393,1667.493) 1132.393,1667.004 ; 1133.6,1670.5 UT2.2@1134.703,1670.504
  TopLayer w0.4: v1(1133,1670.9) 1133.6,1670.5
  TopLayer w0.5: NET.5@1114.178,1685.52 cw(c1113.914,1684.997) 1114.5,1684.997 cw(c1115.291,1684.997) NET.5@1114.772,1685.594 ; NET.5@1114.42,1686.537 ccw(c1114.42,1687.718) 1115.255,1686.883 ; NET.5@1114.455,1685.986 ccw(c1115.468,1685.577) 1114.695,1684.805 ; 1114.525,1684.975 cw(c1113.01,1683.46) NET.4@1115.153,1683.46 ; NET.5@1114.918,1685.799 ccw(c1116.23,1685.27) 1115.23,1684.27 ; NET.5@1114.957,1686 cw(c1116.371,1686) 1115.371,1687 ; NET.4@1115.69,1683.46 1115.69,1683.81 1114.5,1685 1114.5,1686.128 1117.142,1688.77 1120.48,1688.77 1122.467,1686.783 1125.217,1686.783 1127.5,1684.5 ; 1126.82,1685.18 cw(c1125.539,1683.9) C212.2@1127.35,1683.9 ; C210.1@1127.048,1680.067 cw(c1125.957,1678.976) 1127.5,1678.976 cw(c1129.043,1678.976) C210.1@1127.952,1680.067 ; C210.1@1127.048,1681.733 ccw(c1125.957,1682.824) 1127.5,1682.824 ccw(c1129.043,1682.824) C210.1@1127.952,1681.733 ; 1127.25,1684.75 cw(c1126.792,1684.292) C212.2@1127.375,1684.009 ; 1127.5,1683.055 cw(c1128.445,1683.055) C212.2@1127.777,1683.723 ; C212.2@1127.723,1684.118 cw(c1127.939,1684.5) 1127.5,1684.5 ; v1(1133,1676.8) 1131.7,1678.1 1128.1,1678.1 1127.5,1678.7 1127.5,1684.5
  BottomLayer w0.5: v1(1133,1667.1) v1(1133,1676.8)
AVDD33V: C203.1 C205.1 L201.2 UT2.23 UT2.30 UT2.42 | length 35.8
  TopLayer w0.3: 1139.453,1671.647 UT2.42@1139.453,1672.754 ; UT2.23@1141.453,1663.754 1141.453,1664.753 ; 1142.404,1668.004 UT2.30@1143.703,1668.004
  TopLayer w0.5: 1139.453,1671.647 1139.453,1669.847 1141.296,1668.004 1142.6,1668.004 ; 1141.453,1664.753 v1@1141.453,1667.747 ; v1(1149.8,1669.9) 1151.051,1671.151 C203.1@1151.251,1671.151 ; 1150.299,1670.399 cw(c1151.354,1669.343) C203.1@1151.354,1670.836 ; C203.1@1151.082,1671.247 ccw(c1150.556,1671.773) 1151.3,1671.773 ; C205.1@1151.123,1673.523 cw(c1150.696,1673.096) 1151.3,1673.096 cw(c1151.904,1673.096) C205.1@1151.477,1673.523 ; 1151.3,1672.035 ccw(c1152.415,1672.035) C203.1@1151.626,1671.247 ; C205.1@1151.3,1673.7 1151.3,1671.2 1151.2,1671.1 L201.2@1154.175,1671.098 ; C203.1@1151.626,1670.702 cw(c1152.585,1669.742) 1152.586,1671.099 ; C203.1@1151.627,1671.247 ccw(c1151.982,1671.602) C203.1@1151.982,1671.099 ; 1152.686,1671.099 ccw(c1152.687,1672.947) L201.2@1153.992,1671.639 ; 1153.55,1671.098 cw(c1153.55,1670.474) L201.2@1153.992,1670.915
  BottomLayer w0.5: v1(1141.5,1668.004) 1147.904,1668.004 v1(1149.8,1669.9)
B1: 485.2 D421.1 R428.1 | length 28.5
  TopLayer w0.5: R428.1@1207,1651 1209.8,1651 1210.2,1651.4 485.2@1217,1651.4 ; R428.1@1207.041,1651 ccw(c1207.041,1654.359) D421.1@1209.416,1651.984 ; R428.1@1207.227,1650.823 cw(c1207.654,1650.396) 1207.654,1651 cw(c1207.654,1651.604) R428.1@1207.227,1651.177 ; R428.1@1207.524,1651 cw(c1207.524,1648.324) D421.1@1209.416,1650.216 ; 1208.248,1651 ccw(c1208.248,1653.152) D421.1@1209.77,1651.63 ; 1208.731,1651 cw(c1208.731,1649.531) D421.1@1209.77,1650.57 ; D421.1@1210.83,1650.57 cw(c1212.835,1648.565) 1212.835,1651.4 ; D421.1@1211.184,1650.216 cw(c1214.042,1647.358) 1214.042,1651.4 ; D421.1@1211.184,1651.984 ccw(c1212.593,1653.393) 1212.593,1651.4 ; 485.2@1216.22,1650.87 ccw(c1214.939,1649.589) 1214.939,1651.4 ccw(c1214.939,1653.211) 485.2@1216.22,1651.93
CAM_CLKOUT: CAMERA_A1.8 CAMERA_A2.8 J1.22 | length 107.6
  TopLayer w0.135: 1083.6,1615.6 1087.6,1615.6 1088,1615.2 J1.22@1090.4,1615.2
  TopLayer w0.2: CAMERA_A2.8@1051.8,1605.4 1053.3,1605.4 1054.9,1607 1071.9,1607 1080.5,1615.6 1083.6,1615.6 ; CAMERA_A2.8@1052.012,1605.188 cw(c1052.524,1604.676) 1052.524,1605.4 cw(c1052.524,1606.124) CAMERA_A2.8@1052.012,1605.612 ; CAMERA_A2.8@1052.154,1605.046 cw(c1053.007,1604.193) 1053.007,1605.4 cw(c1053.007,1606.607) CAMERA_A2.8@1052.154,1605.754 ; J1.22@1090.4,1615.2 1093.507,1615.2 1095.3,1613.407 1095.3,1580.825 1098.525,1577.6 1105.8,1577.6 1109.8,1573.6 1109.8,1572.2 CAMERA_A1.8@1110.8,1571.2 ; CAMERA_A1.8@1110.3,1571.2 ccw(c1109.093,1571.2) 1109.946,1572.054 ccw(c1110.8,1572.907) CAMERA_A1.8@1110.8,1571.7 ; CAMERA_A1.8@1110.5,1571.2 ccw(c1109.776,1571.2) 1110.288,1571.712 ccw(c1110.8,1572.224) CAMERA_A1.8@1110.8,1571.5
CAM_FILELD: J1.26 RM5.1 RM6.1 | length 60.4
  TopLayer w0.2: J1.26@1090.4,1616.8 1094.269,1616.8 1096.9,1614.169 1096.9,1581.488 1099.188,1579.2 1109.3,1579.2 RM5.1@1110,1578.5 RM6.1@1111.4,1578.5 ; 1109.325,1579.175 ccw(c1109.882,1579.732) RM5.1@1109.96,1578.948 ; 1109.353,1579.147 cw(c1108.755,1578.55) RM5.1@1109.6,1578.55 ; RM5.1@1110.283,1578.217 cw(c1110.966,1577.534) 1110.966,1578.5 cw(c1110.966,1579.466) RM5.1@1110.283,1578.783 ; RM6.1@1111.117,1578.217 ccw(c1110.434,1577.534) 1110.434,1578.5 ccw(c1110.434,1579.466) RM6.1@1111.117,1578.783
CAM_HREF: CAMERA_A1.6 CAMERA_A2.6 J1.24 | length 109.4
  TopLayer w0.135: 1083.6,1616.4 1087.7,1616.4 1088.1,1616 J1.24@1090.4,1616
  TopLayer w0.2: CAMERA_A2.6@1051.8,1607.4 1053.3,1607.4 1053.9,1608 1071.6,1608 1080,1616.4 1083.6,1616.4 ; CAMERA_A2.6@1052.012,1607.188 cw(c1052.524,1606.676) 1052.524,1607.4 cw(c1052.524,1608.124) CAMERA_A2.6@1052.012,1607.612 ; CAMERA_A2.6@1052.154,1607.046 cw(c1053.007,1606.193) 1053.007,1607.4 cw(c1053.007,1608.607) CAMERA_A2.6@1052.154,1607.754 ; J1.24@1090.4,1616 1093.875,1616 1096.1,1613.775 1096.1,1581.157 1098.857,1578.4 1106.2,1578.4 1110.2,1574.4 1111,1574.4 1111.8,1573.6 1111.8,1572.2 CAMERA_A1.6@1112.8,1571.2 ; CAMERA_A1.6@1112.3,1571.2 ccw(c1111.093,1571.2) 1111.946,1572.054 ccw(c1112.8,1572.907) CAMERA_A1.6@1112.8,1571.7 ; CAMERA_A1.6@1112.5,1571.2 ccw(c1111.776,1571.2) 1112.288,1571.712 ccw(c1112.8,1572.224) CAMERA_A1.6@1112.8,1571.5
CAM_IO: CAMERA_A1.3 RM5.2 | length 11.4
  TopLayer w0.2: RM5.2@1109.717,1576.417 cw(c1109.034,1575.734) 1110,1575.734 cw(c1110.966,1575.734) RM5.2@1110.283,1576.417 ; RM5.2@1110,1576.75 1110,1575.731 1110.531,1575.2 1112.8,1575.2 CAMERA_A1.3@1114.8,1573.2 ; CAMERA_A1.3@1114.3,1573.2 ccw(c1113.093,1573.2) 1113.946,1574.054 ccw(c1114.8,1574.907) CAMERA_A1.3@1114.8,1573.7 ; CAMERA_A1.3@1114.5,1573.2 ccw(c1113.776,1573.2) 1114.288,1573.712 ccw(c1114.8,1574.224) CAMERA_A1.3@1114.8,1573.5
CAM_PCLK: CAMERA_A1.5 CAMERA_A2.5 J1.25 | length 107.1
  TopLayer w0.135: J1.25@1085.2,1616.8 1086.6,1616.8 1086.734,1616.666 1087.934,1616.666 1088.2,1616.4 1092,1616.4
  TopLayer w0.2: CAMERA_A2.5@1049.8,1607.4 1050.8,1608.4 1071.35,1608.4 1079.75,1616.8 J1.25@1085.2,1616.8 ; CAMERA_A2.5@1049.8,1607.7 ccw(c1049.8,1608.424) 1050.312,1607.912 ccw(c1050.824,1607.4) CAMERA_A2.5@1050.1,1607.4 ; CAMERA_A2.5@1049.8,1607.9 ccw(c1049.8,1609.107) 1050.654,1608.254 ccw(c1051.507,1607.4) CAMERA_A2.5@1050.3,1607.4 ; 1092,1616.4 1094.085,1616.4 1096.5,1613.985 1096.5,1581.323 1099.023,1578.8 1106.366,1578.8 1110.366,1574.8 1111.2,1574.8 CAMERA_A1.5@1112.8,1573.2
CAM_SCL: CAMERA_A1.2 CAMERA_A2.2 RM1.1 RM19.2 RM24.1 | length 121.5
  TopLayer w0.2: CAMERA_A1.2@1116.8,1571.2 1118.4,1572.8 RM24.1@1118.4,1576.748 ; CAMERA_A1.2@1116.8,1571.5 ccw(c1116.8,1572.224) 1117.312,1571.712 ccw(c1117.824,1571.2) CAMERA_A1.2@1117.1,1571.2 ; CAMERA_A1.2@1116.8,1571.7 ccw(c1116.8,1572.907) 1117.654,1572.054 ccw(c1118.507,1571.2) CAMERA_A1.2@1117.3,1571.2 ; RM19.2@1117.005,1576.7 RM1.1@1119.852,1576.7 ; RM19.2@1117.288,1576.417 cw(c1117.971,1575.734) 1117.971,1576.7 cw(c1117.971,1577.666) RM19.2@1117.288,1576.983 ; RM19.2@1117.43,1576.7 cw(c1117.43,1575.728) 1118.117,1576.415 cw(c1117.434,1575.733) 1118.4,1575.733 cw(c1119.366,1575.733) 1118.683,1576.415 cw(c1119.37,1575.728) RM1.1@1119.37,1576.7 ; RM19.2@1117.439,1576.7 ccw(c1117.439,1577.66) RM24.1@1118.117,1576.981 ; RM24.1@1118.683,1576.981 ccw(c1119.361,1577.66) RM1.1@1119.361,1576.7 ; RM24.1@1118.83,1576.7 cw(c1118.83,1575.728) RM1.1@1119.517,1576.415 ; RM24.1@1118.839,1576.7 ccw(c1118.839,1577.66) RM1.1@1119.517,1576.981
  BottomLayer w0.2: CAMERA_A2.2@1051.3,1611.4 ccw(c1050.093,1611.4) 1050.946,1612.254 ccw(c1051.8,1613.107) CAMERA_A2.2@1051.8,1611.9 ; CAMERA_A2.2@1051.5,1611.4 ccw(c1050.776,1611.4) 1051.288,1611.912 ccw(c1051.8,1612.424) CAMERA_A2.2@1051.8,1611.7 ; CAMERA_A2.2@1051.8,1611.4 1050.757,1612.443 1049.071,1612.443 1048.182,1611.554 1048.182,1605.534 1049.325,1604.391 1061.309,1604.391 1074.9,1590.8 1096.945,1590.8 1109.364,1578.381 1113.91,1578.381 1115.771,1576.52 1115.771,1572.229 CAMERA_A1.2@1116.8,1571.2 ; CAMERA_A1.2@1116.3,1571.2 ccw(c1115.093,1571.2) 1115.946,1572.054 ccw(c1116.8,1572.907) CAMERA_A1.2@1116.8,1571.7 ; CAMERA_A1.2@1116.5,1571.2 ccw(c1115.776,1571.2) 1116.288,1571.712 ccw(c1116.8,1572.224) CAMERA_A1.2@1116.8,1571.5
CAM_SDA: CAMERA_A1.1 CAMERA_A2.1 RM3.1 RM20.2 RM25.1 | length 115
  TopLayer w0.2: RM3.1@1120.917,1576.415 cw(c1120.234,1575.733) 1121.2,1575.733 cw(c1122.166,1575.733) RM3.1@1121.483,1576.415 ; v2(1121.2,1575.4) RM3.1@1121.2,1576.748 ; RM3.1@1121.252,1576.8 RM20.2@1124.005,1576.8 ; RM3.1@1121.483,1576.515 cw(c1122.17,1575.828) RM25.1@1122.17,1576.8 ; RM3.1@1121.483,1577.081 ccw(c1122.161,1577.76) RM25.1@1122.161,1576.8 ; RM3.1@1121.63,1576.8 cw(c1121.63,1575.828) RM25.1@1122.317,1576.515 ; RM3.1@1121.639,1576.8 ccw(c1121.639,1577.76) RM25.1@1122.317,1577.081 ; RM25.1@1122.883,1576.515 cw(c1123.57,1575.828) RM20.2@1123.57,1576.8 ; RM25.1@1122.883,1577.081 ccw(c1123.561,1577.76) RM20.2@1123.561,1576.8 ; RM20.2@1123.723,1576.517 ccw(c1123.04,1575.834) 1123.04,1576.8 ccw(c1123.04,1577.766) RM20.2@1123.723,1577.083
  BottomLayer w0.2: CAMERA_A2.1@1049.3,1611.4 cw(c1048.093,1611.4) 1048.946,1610.546 cw(c1049.8,1609.693) CAMERA_A2.1@1049.8,1610.9 ; CAMERA_A2.1@1049.5,1611.4 cw(c1048.776,1611.4) 1049.288,1610.888 cw(c1049.8,1610.376) CAMERA_A2.1@1049.8,1611.1 ; CAMERA_A2.1@1049.8,1611.4 1048.588,1610.188 1048.588,1606.855 1049.071,1606.372 1059.893,1606.372 1075.066,1591.2 1097.111,1591.2 1109.511,1578.8 1114.057,1578.8 1116.8,1576.057 CAMERA_A1.1@1116.8,1573.2 1119,1573.2 v2(1121.2,1575.4) ; CAMERA_A1.1@1116.446,1573.554 ccw(c1115.593,1574.407) 1116.8,1574.407 ccw(c1118.007,1574.407) 1117.154,1573.554 ccw(c1118.007,1574.407) 1118.007,1573.2 ccw(c1118.007,1571.993) CAMERA_A1.1@1117.154,1572.846 ; CAMERA_A1.1@1116.588,1573.412 ccw(c1116.076,1573.924) 1116.8,1573.924 ccw(c1117.524,1573.924) 1117.012,1573.412 ccw(c1117.524,1573.924) 1117.524,1573.2 ccw(c1117.524,1572.476) CAMERA_A1.1@1117.012,1572.988
CAM_VSYNC: CAMERA_A1.7 CAMERA_A2.7 J1.23 | length 105.3
  TopLayer w0.135: J1.23@1085.1,1616 1087.6,1616 1088,1615.6 1092,1615.6
  TopLayer w0.2: CAMERA_A2.7@1049.8,1605.4 1050.8,1606.4 1053.3,1606.4 1054.4,1607.5 1071.75,1607.5 1080.25,1616 J1.23@1085.2,1616 ; CAMERA_A2.7@1049.8,1605.7 ccw(c1049.8,1606.424) 1050.312,1605.912 ccw(c1050.824,1605.4) CAMERA_A2.7@1050.1,1605.4 ; CAMERA_A2.7@1049.8,1605.9 ccw(c1049.8,1607.107) 1050.654,1606.254 ccw(c1051.507,1605.4) CAMERA_A2.7@1050.3,1605.4 ; 1092,1615.6 1093.691,1615.6 1095.7,1613.591 1095.7,1580.991 1098.691,1578 1106,1578 CAMERA_A1.7@1110.8,1573.2
CAMARSTN: CAMERA_A1.4 RM21.2 RM22.2 RM23.2 | length 23.2
  TopLayer w0.2: RM21.2@1112.795,1578.05 cw(c1112.795,1577.433) 1113.231,1577.869 ; RM21.2@1112.795,1578.5 1112.795,1578.305 RM22.2@1114.1,1577 ; RM21.2@1112.995,1578.45 ccw(c1113.826,1578.45) 1113.238,1577.862 ; RM21.2@1113.195,1578.45 ccw(c1114.509,1578.45) 1113.58,1577.52 ; 1113.41,1577.69 cw(c1112.468,1576.748) RM22.2@1113.8,1576.748 ; 1113.751,1577.349 cw(c1113.151,1576.748) RM22.2@1114,1576.748 ; 1113.776,1577.324 ccw(c1114.2,1577.747) RM22.2@1114.2,1577.148 ; RM22.2@1114.2,1576.698 1115.502,1576.698 RM23.2@1115.8,1576.4 ; RM22.2@1114.483,1576.415 cw(c1115.166,1575.733) 1115.166,1576.698 cw(c1115.166,1577.664) RM22.2@1114.483,1576.981 ; CAMERA_A1.4@1114.8,1571.2 1115.8,1572.2 RM23.2@1115.8,1576.8 ; CAMERA_A1.4@1114.8,1571.5 ccw(c1114.8,1572.224) 1115.312,1571.712 ccw(c1115.824,1571.2) CAMERA_A1.4@1115.1,1571.2 ; CAMERA_A1.4@1114.8,1571.7 ccw(c1114.8,1572.907) 1115.654,1572.054 ccw(c1116.507,1571.2) CAMERA_A1.4@1115.3,1571.2 ; RM23.2@1115.317,1576.365 cw(c1114.151,1575.2) 1115.8,1575.2 ; RM23.2@1115.317,1576.415 ccw(c1114.634,1575.733) 1114.634,1576.698 ccw(c1114.634,1577.664) RM23.2@1115.317,1576.981 ; RM23.2@1115.398,1576.7 RM23.2@1115.4,1576.698 ; RM23.2@1115.459,1576.507 cw(c1114.634,1575.683) 1115.8,1575.683 ; RM23.2@1115.6,1576.648 cw(c1115.117,1576.165) 1115.8,1576.165 cw(c1116.083,1576.165) RM23.2@1115.883,1576.365
CAMB_IO: CAMERA_A2.3 CAMERA_B.3 RMB5.2 | length 116.6
  TopLayer w0.2: v2(1141.4,1577.6) 1142.25,1576.75 RMB5.2@1143.1,1576.75 1143.1,1573.9 ; RMB5.2@1142.817,1576.417 cw(c1142.134,1575.734) 1143.1,1575.734 cw(c1144.066,1575.734) RMB5.2@1143.383,1576.417 ; CAMERA_B.3@1143.306,1573.275 ccw(c1142.584,1573.384) 1143.1,1573.9 ; CAMERA_B.3@1143.725,1573.694 cw(c1143.616,1574.416) 1143.1,1573.9 ; CAMERA_B.3@1143.8,1573.2 1143.1,1573.9
  BottomLayer w0.2: CAMERA_A2.3@1049.8,1608.9 cw(c1049.8,1607.693) 1050.654,1608.546 cw(c1051.507,1609.4) CAMERA_A2.3@1050.3,1609.4 ; CAMERA_A2.3@1049.8,1609.1 cw(c1049.8,1608.376) 1050.312,1608.888 cw(c1050.824,1609.4) CAMERA_A2.3@1050.1,1609.4 ; CAMERA_A2.3@1049.8,1609.4 1050.796,1608.404 1058.427,1608.404 1075.231,1591.6 1113.627,1591.6 1121.727,1583.5 1125.5,1583.5 1130.1,1578.9 1140.092,1578.9 v2(1141.4,1577.6)
CAMB_SCL: CAMERA_B.2 RMB1.1 | length 12.7
  TopLayer w0.2: CAMERA_B.2@1145.8,1571.2 1148.5,1573.9 RMB1.1@1148.5,1576.8 ; CAMERA_B.2@1145.8,1571.5 ccw(c1145.8,1572.224) 1146.312,1571.712 ccw(c1146.824,1571.2) CAMERA_B.2@1146.1,1571.2 ; CAMERA_B.2@1145.8,1571.7 ccw(c1145.8,1572.907) 1146.654,1572.054 ccw(c1147.507,1571.2) CAMERA_B.2@1146.3,1571.2 ; RMB1.1@1148.417,1576.467 cw(c1148.217,1576.267) 1148.5,1576.267 cw(c1149.183,1576.267) RMB1.1@1148.7,1576.75 ; 1148.5,1575.301 cw(c1150.149,1575.301) RMB1.1@1148.983,1576.467 ; 1148.5,1575.784 cw(c1149.666,1575.784) RMB1.1@1148.841,1576.609
CAMB_SDA: CAMERA_B.1 RMB3.1 | length 8.8
  TopLayer w0.2: CAMERA_B.1@1145.8,1573.2 1147.3,1574.7 RMB3.1@1147.3,1576.8 ; CAMERA_B.1@1145.8,1573.5 ccw(c1145.8,1574.224) 1146.312,1573.712 ccw(c1146.824,1573.2) CAMERA_B.1@1146.1,1573.2 ; CAMERA_B.1@1145.8,1573.7 ccw(c1145.8,1574.907) 1146.654,1574.054 ccw(c1147.507,1573.2) CAMERA_B.1@1146.3,1573.2 ; RMB3.1@1147.017,1576.467 cw(c1146.334,1575.784) 1147.3,1575.784 cw(c1148.266,1575.784) RMB3.1@1147.583,1576.467
CAMBRSTN: CAMERA_A2.4 CAMERA_B.4 RMB21.2 RMB22.2 RMB23.1 | length 134.9
  TopLayer w0.2: CAMERA_B.4@1143.8,1571.2 1144.8,1572.2 RMB22.2@1144.8,1576.7 ; CAMERA_B.4@1143.8,1571.5 ccw(c1143.8,1572.224) 1144.312,1571.712 ccw(c1144.824,1571.2) CAMERA_B.4@1144.1,1571.2 ; CAMERA_B.4@1143.8,1571.7 ccw(c1143.8,1572.907) 1144.654,1572.054 ccw(c1145.507,1571.2) CAMERA_B.4@1144.3,1571.2 ; RMB22.2@1144.217,1576.417 cw(c1142.81,1575.01) 1144.8,1575.01 ; RMB22.2@1144.359,1576.559 cw(c1143.293,1575.493) 1144.8,1575.493 ; RMB22.2@1144.4,1576.9 1145.9,1578.4 RMB23.1@1145.9,1580.3 ; RMB22.2@1144.5,1576.7 cw(c1143.776,1575.976) 1144.8,1575.976 ; RMB22.2@1144.5,1577.2 ccw(c1144.5,1577.683) 1144.841,1577.341 ; RMB22.2@1144.7,1576.8 cw(c1145.666,1576.8) 1144.983,1577.483 ; RMB22.2@1144.9,1576.8 cw(c1146.349,1576.8) 1145.324,1577.824 ; 1145.146,1577.646 ccw(c1144.293,1578.5) RMB21.2@1145.5,1578.5 ; 1145.388,1577.888 cw(c1145.9,1577.376) RMB21.2@1145.9,1578.1 ; 1145.488,1577.988 ccw(c1144.976,1578.5) RMB21.2@1145.7,1578.5 ; RMB23.1@1145.517,1580.167 cw(c1144.593,1579.243) v2@1145.9,1579.243 ; RMB21.2@1145.617,1578.883 ccw(c1144.934,1579.566) 1145.9,1579.566 ccw(c1146.866,1579.566) RMB21.2@1146.183,1578.883 ; RMB23.1@1145.659,1580.309 cw(c1145.076,1579.726) 1145.9,1579.726 cw(c1146.524,1579.726) RMB23.1@1146.083,1580.167
  BottomLayer w0.2: CAMERA_A2.4@1051.8,1609.4 1057.997,1609.4 1075.397,1592 1113.8,1592 1121.8,1584 1125.7,1584 1130.4,1579.3 1143,1579.3 1143.9,1578.4 1145,1578.4 v2(1145.9,1579.3) ; CAMERA_A2.4@1052.012,1609.188 cw(c1052.524,1608.676) 1052.524,1609.4 cw(c1052.524,1610.124) CAMERA_A2.4@1052.012,1609.612 ; CAMERA_A2.4@1052.154,1609.046 cw(c1053.007,1608.193) 1053.007,1609.4 cw(c1053.007,1610.607) CAMERA_A2.4@1052.154,1609.754
CAMDATA0: CAMERA_A1.16 CAMERA_A2.16 J1.14 | length 100.1
  TopLayer w0.135: 1083.6,1612.4 1086.8,1612.4 1087.2,1612 J1.14@1090.4,1612
  TopLayer w0.2: CAMERA_A2.16@1051.8,1597.4 1053.3,1597.4 1058.9,1603 1073.1,1603 1082.5,1612.4 1083.6,1612.4 ; CAMERA_A2.16@1052.012,1597.188 cw(c1052.524,1596.676) 1052.524,1597.4 cw(c1052.524,1598.124) CAMERA_A2.16@1052.012,1597.612 ; CAMERA_A2.16@1052.154,1597.046 cw(c1053.007,1596.193) 1053.007,1597.4 cw(c1053.007,1598.607) CAMERA_A2.16@1052.154,1597.754 ; J1.14@1090.4,1612 1091.8,1612 1092.1,1611.7 1092.1,1579.5 1097.2,1574.4 1101.1,1574.4 1101.8,1573.7 1101.8,1572.2 CAMERA_A1.16@1102.8,1571.2 ; CAMERA_A1.16@1102.3,1571.2 ccw(c1101.093,1571.2) 1101.946,1572.054 ccw(c1102.8,1572.907) CAMERA_A1.16@1102.8,1571.7 ; CAMERA_A1.16@1102.5,1571.2 ccw(c1101.776,1571.2) 1102.288,1571.712 ccw(c1102.8,1572.224) CAMERA_A1.16@1102.8,1571.5
CAMDATA1: CAMERA_A1.15 CAMERA_A2.15 J1.15 | length 97.7
  TopLayer w0.135: J1.15@1085.2,1612.8 1086.9,1612.8 1087.3,1612.4 1092,1612.4
  TopLayer w0.2: CAMERA_A2.15@1049.8,1597.4 1050.7,1598.3 1053.3,1598.3 1058.5,1603.5 1072.95,1603.5 1082.25,1612.8 J1.15@1085.2,1612.8 ; CAMERA_A2.15@1049.8,1597.7 ccw(c1049.8,1598.424) 1050.312,1597.912 ccw(c1050.824,1597.4) CAMERA_A2.15@1050.1,1597.4 ; CAMERA_A2.15@1049.8,1597.9 ccw(c1049.8,1599.107) 1050.654,1598.254 ccw(c1051.507,1597.4) CAMERA_A2.15@1050.3,1597.4 ; 1092,1612.4 1092.167,1612.4 1092.5,1612.067 1092.5,1579.666 1097.366,1574.8 1101.4,1574.8 CAMERA_A1.15@1102.8,1573.4
CAMDATA2: CAMERA_A1.14 CAMERA_A2.14 J1.16 | length 102.1
  TopLayer w0.135: 1083.6,1613.2 1087,1613.2 1087.4,1612.8 J1.16@1090.4,1612.8
  TopLayer w0.2: CAMERA_A2.14@1051.8,1599.4 1053.3,1599.4 1057.9,1604 1072.8,1604 1082,1613.2 1083.6,1613.2 ; CAMERA_A2.14@1052.012,1599.188 cw(c1052.524,1598.676) 1052.524,1599.4 cw(c1052.524,1600.124) CAMERA_A2.14@1052.012,1599.612 ; CAMERA_A2.14@1052.154,1599.046 cw(c1053.007,1598.193) 1053.007,1599.4 cw(c1053.007,1600.607) CAMERA_A2.14@1052.154,1599.754 ; J1.16@1090.4,1612.8 1092.351,1612.8 1092.9,1612.251 1092.9,1579.831 1097.531,1575.2 1102.3,1575.2 1103.8,1573.7 1103.8,1572.2 CAMERA_A1.14@1104.8,1571.2 ; CAMERA_A1.14@1104.3,1571.2 ccw(c1103.093,1571.2) 1103.946,1572.054 ccw(c1104.8,1572.907) CAMERA_A1.14@1104.8,1571.7 ; CAMERA_A1.14@1104.5,1571.2 ccw(c1103.776,1571.2) 1104.288,1571.712 ccw(c1104.8,1572.224) CAMERA_A1.14@1104.8,1571.5
CAMDATA3: CAMERA_A1.13 CAMERA_A2.13 J1.17 | length 103.5
  TopLayer w0.12: J1.17@1085.2,1613.6 J1.17@1085.3,1613.6
  TopLayer w0.135: J1.17@1085.3,1613.6 1087.1,1613.6 1087.5,1613.2 1092,1613.2
  TopLayer w0.2: CAMERA_A2.13@1049.8,1599.4 1050.8,1600.4 1053.3,1600.4 1057.4,1604.5 1072.65,1604.5 1081.75,1613.6 J1.17@1085.2,1613.6 ; CAMERA_A2.13@1049.8,1599.7 ccw(c1049.8,1600.424) 1050.312,1599.912 ccw(c1050.824,1599.4) CAMERA_A2.13@1050.1,1599.4 ; CAMERA_A2.13@1049.8,1599.9 ccw(c1049.8,1601.107) 1050.654,1600.254 ccw(c1051.507,1599.4) CAMERA_A2.13@1050.3,1599.4 ; 1092,1613.2 1092.535,1613.2 1093.3,1612.435 1093.3,1579.997 1097.697,1575.6 1102.7,1575.6 CAMERA_A1.13@1104.9,1573.4 ; 1103.734,1574.566 cw(c1102.369,1573.2) CAMERA_A1.13@1104.3,1573.2 ; 1104.076,1574.224 cw(c1103.051,1573.2) CAMERA_A1.13@1104.5,1573.2 ; 1104.417,1573.883 cw(c1103.734,1573.2) CAMERA_A1.13@1104.7,1573.2 ; 1104.459,1573.841 ccw(c1104.8,1574.183) CAMERA_A1.13@1104.8,1573.7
